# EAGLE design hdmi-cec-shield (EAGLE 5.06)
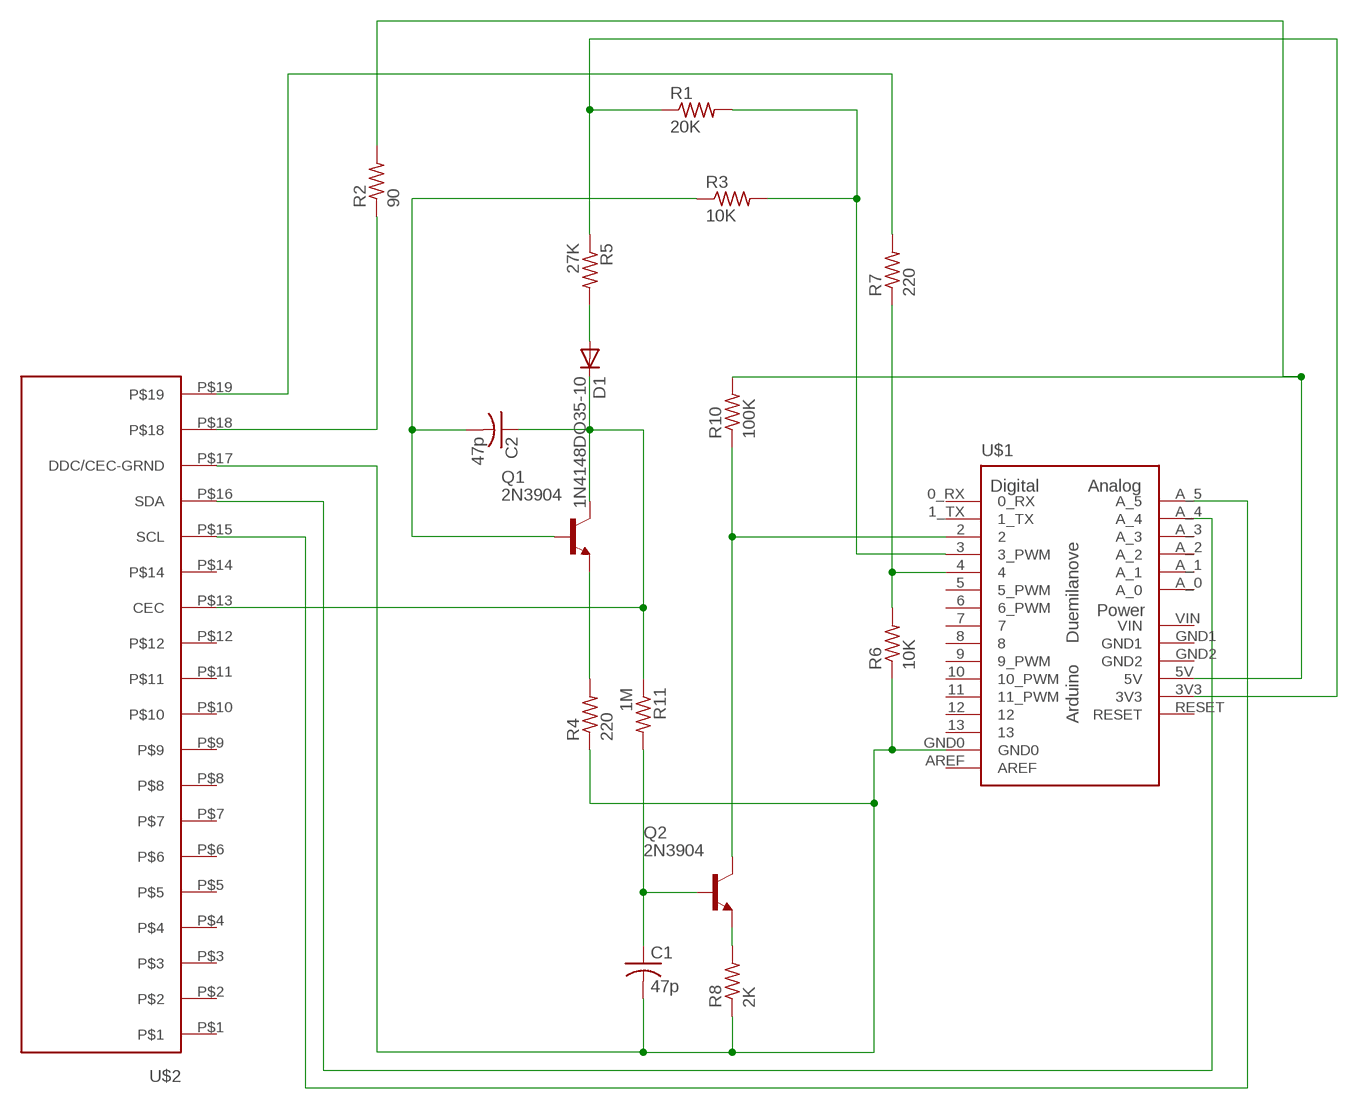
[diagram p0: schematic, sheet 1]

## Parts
C1  47p  C-US050-025X075  [C050-025X075]
C2  47p  C-US050-025X075  [C050-025X075]
D1  1N4148DO35-10  [DO35-10]
Q1  2N3904  [TO92]
Q2  2N3904  [TO92]
R1  20K  R-US_0207/10  [0207/10]
R2  90  R-US_0207/10  [0207/10]
R3  10K  R-US_0207/10  [0207/10]
R4  220  R-US_0207/10  [0207/10]
R5  27K  R-US_0207/10  [0207/10]
R6  10K  R-US_0207/10  [0207/10]
R7  220  R-US_0207/10  [0207/10]
R8  2K  R-US_0207/10  [0207/10]
R10  100K  R-US_0207/10  [0207/10]
R11  1M  R-US_0207/10  [0207/10]
U$1  ARDUINO-USBLONG_PADS_TEXT  [SHIELD]
U$2  HDMI-TYPE-A-RECEPTICALFCI10029449  [FCI-HDMI-TYPE-A-RECEPT]

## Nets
3.3V: R1.1 R5.1 U$1.3V3
5V: R2.2 R10.2 U$1.5V
GND0: C1.2 R4.1 R6.1 R8.1 U$1.GND0 U$2.P$17(DDC/CEC-GRND)
N$1: C2.2 Q1.2(B) R3.1
N$2: C1.1 Q2.2(B) R11.2
N$3: Q2.3(E) R8.2
N$4: Q2.1(C) R10.1 U$1.2
N$5: R2.1 U$2.P$18
N$6: C2.1 D1.C Q1.1(C) R11.1 U$2.P$13(CEC)
N$7: Q1.3(E) R4.2
N$8: R1.2 R3.2 U$1.3(3_PWM)
N$9: D1.A R5.2
N$10: R7.2 U$2.P$19
N$13: R6.2 R7.1 U$1.4
SCL: U$1.A_5 U$2.P$15(SCL)
SDA: U$1.A_4 U$2.P$16(SDA)
Unconnected: U$1.0_RX U$1.1_TX U$1.5(5_PWM) U$1.6(6_PWM) U$1.7 U$1.8 U$1.9(9_PWM) U$1.10(10_PWM) U$1.11(11_PWM) U$1.12 U$1.13 U$1.A_0 U$1.A_1 U$1.A_2 U$1.A_3 U$1.AREF U$1.GND1 U$1.GND2 U$1.RESET U$2.P$1 U$2.P$2 U$2.P$3 U$2.P$4 U$2.P$5 U$2.P$6 U$2.P$7 U$2.P$8 U$2.P$9 U$2.P$10 U$2.P$11 U$2.P$12 U$2.P$14

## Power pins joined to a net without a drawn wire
VIN: U$1.VIN

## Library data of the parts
C1 C2 = resistor:C-US: CAPACITOR, American symbol
D1 = diode:1N4148: DIODE
Q1 Q2 = transistor-neu-to92:2N3904: NPN TRANSISTOR
R1-R8 R10 R11 = resistor:R-US_: RESISTOR, American symbol
U$1 = Arduino-Various:ARDUINO-USB: The Ardiuno Duemilanove Pinouts layoutet as a Bare Shield. v0.5 Also for Arduino Diecimila. This is designed as a Part and has no Outline in the Dimension Layer. The Outline, when present, is drawed at the tPlace / bPlace Layer. Library by Stephanie Lange, http://www.k-ita.de/~sl/
U$2 = hdmi:HDMI-TYPE-A-RECEPTICAL

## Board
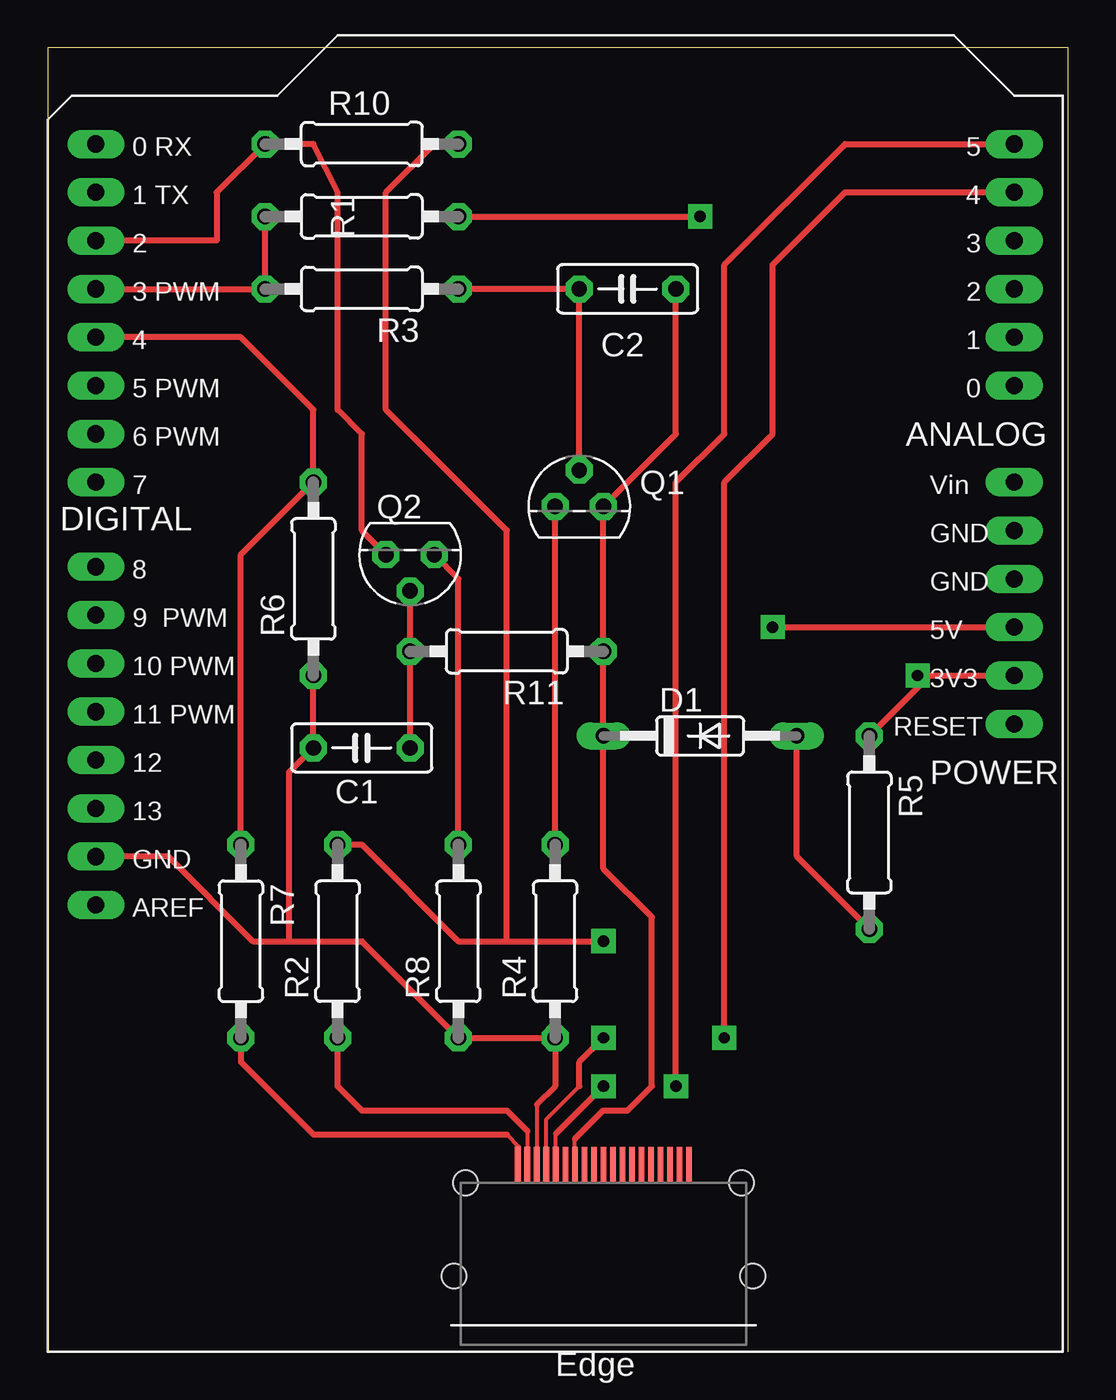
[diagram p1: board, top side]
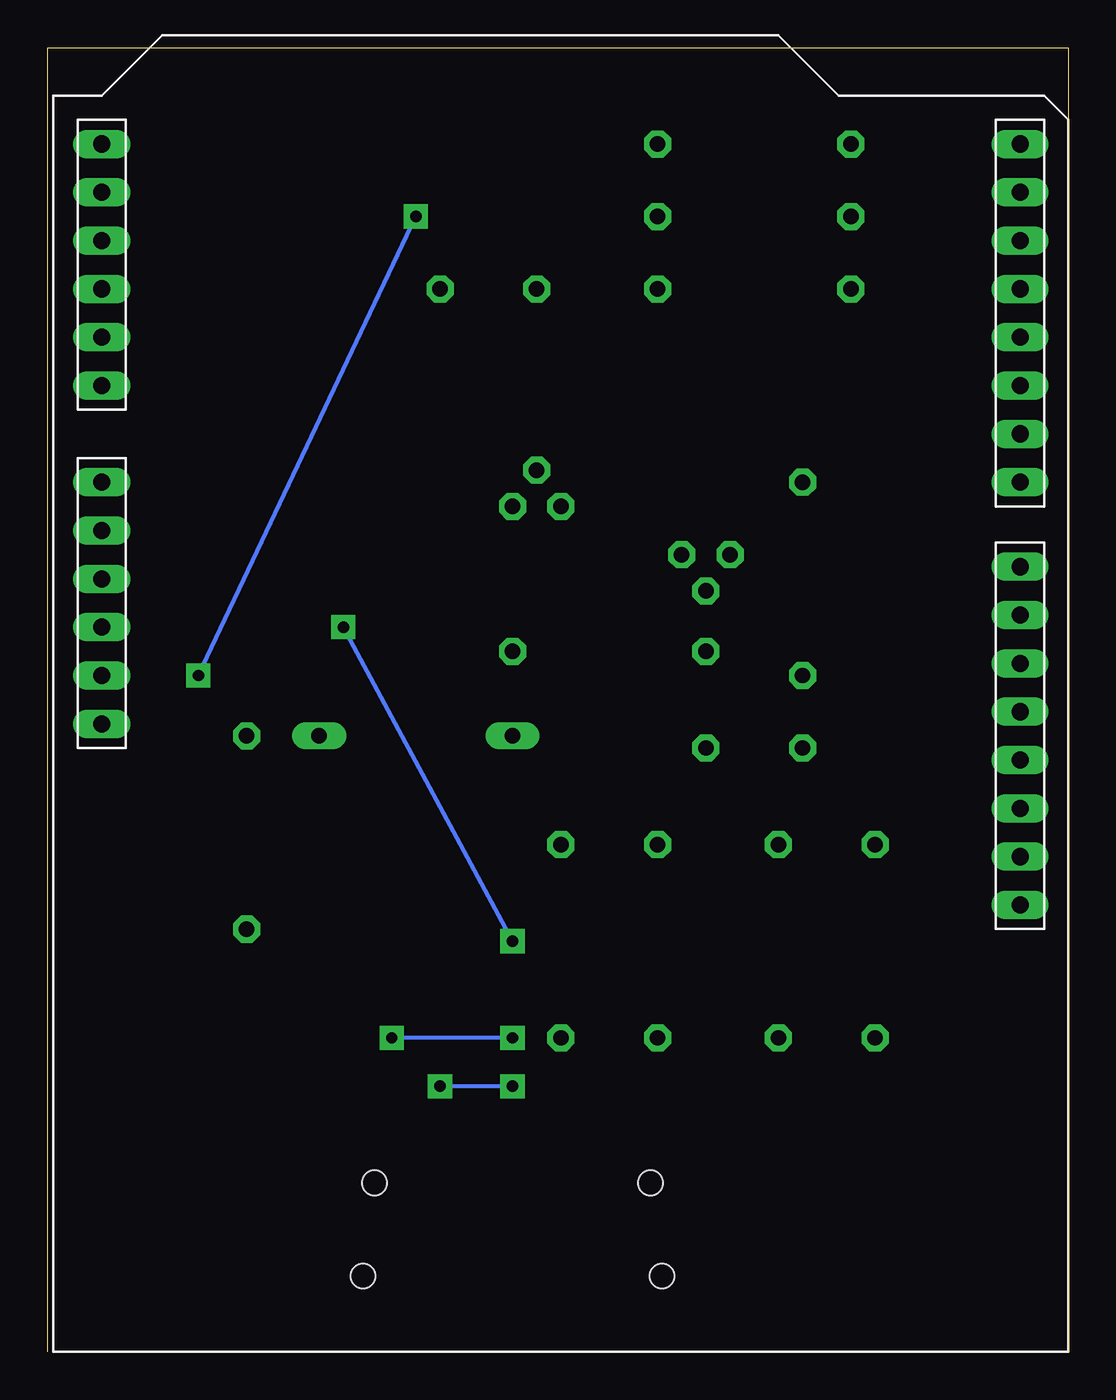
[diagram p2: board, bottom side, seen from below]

Size 53.65 x 68.57 mm. Coordinates in mm from the lower left corner, seen from the top.
Outline: 53.65,0 53.65,68.57 0,68.57 0,0
Copper layers (1*16): Top 0.035mm / dielectric 1.5mm / Bottom 0.035mm
Design rules "default *": minimum track width 10mil, minimum drill 24mil, track to track 8mil, track to pad 8mil, pad to pad 8mil, via to via 8mil, smd to smd 8mil, copper to edge 40mil, drill to drill 8mil, minimum pad ring 12mil, minimum via ring 8mil, stop-mask expansion 4mil, vias tented up to drill 0mil, thermal gap 10mil

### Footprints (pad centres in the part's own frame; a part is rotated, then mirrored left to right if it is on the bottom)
C050-025X075 = drill 0.813 octagon: 1 -2.54,0; 2 2.54,0
DO35-10 = drill 0.813 long: A 5.08,0; C -5.08,0
TO92 = drill 0.813 octagon: 1 1.27,0; 2 0,1.905; 3 -1.27,0
0207/10 = drill 0.813 octagon: 1 -5.08,0; 2 5.08,0
SHIELD = drill 0.9 pad 1.27 long: 0_RX -25.4,27.94; 1_TX -25.4,25.4; 2 -25.4,22.86; 3 -25.4,20.32; 3V3 22.86,0; 4 -25.4,17.78; 5 -25.4,15.24; 5V 22.86,2.54; 6 -25.4,12.7; 7 -25.4,10.16; 8 -25.4,5.715; 9 -25.4,3.175; 10 -25.4,0.635; 11 -25.4,-1.905; 12 -25.4,-4.445; 13 -25.4,-6.985; A_0 22.86,15.24; A_1 22.86,17.78; A_2 22.86,20.32; A_3 22.86,22.86; A_4 22.86,25.4; A_5 22.86,27.94; AREF -25.4,-12.065; GND0 -25.4,-9.525; GND1 22.86,7.62; GND2 22.86,5.08; RESET 22.86,-2.54; VIN 22.86,10.16
FCI-HDMI-TYPE-A-RECEPT = smd 1.9 x 0.3: P$1 -0.95,4.5; P$2 -0.95,4; P$3 -0.95,3.5; P$4 -0.95,3; P$5 -0.95,2.5; P$6 -0.95,2; P$7 -0.95,1.5; P$8 -0.95,1; P$9 -0.95,0.5; P$10 -0.95,0; P$11 -0.95,-0.5; P$12 -0.95,-1; P$13 -0.95,-1.5; P$14 -0.95,-2; P$15 -0.95,-2.5; P$16 -0.95,-3; P$17 -0.95,-3.5; P$18 -0.95,-4; P$19 -0.95,-4.5 | hole 1.3: 0,7.25; 0,-7.25; 4.9,7.85; 4.9,-7.85

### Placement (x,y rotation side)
C1  16.51,31.75 180 top
C2  30.48,55.88 180 top
D1  34.29,32.39 0 top
Q1  27.94,44.45 0 top
Q2  19.05,41.91 180 top
R1  16.51,59.69 180 top
R2  15.24,21.59 90 top
R3  16.51,55.88 180 top
R4  26.67,21.59 90 top
R5  43.18,27.3 270 top
R6  13.97,40.64 90 top
R7  10.16,21.59 270 top
R8  21.59,21.59 90 top
R10  16.51,63.5 0 top
R11  24.13,36.83 180 top
U$1  27.94,35.56 0 top
U$2  29.21,8.89 270 top

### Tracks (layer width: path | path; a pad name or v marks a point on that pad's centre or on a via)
3.3V  (via drill 0.6, 0.6 pad 1.27)
  Top 0.203: 46.35,35.56 v45.72,35.56
  Top 0.305: U$1.3V3 46.35,35.56 R5.1 | R1.1 v34.29,59.69
  Bottom 0.203: v45.72,35.56 v34.29,59.69
5V  (via drill 0.6, 0.6 pad 1.27)
  Top 0.305: R2.2 16.51,26.67 21.59,21.59 24.13,21.59 | 24.13,21.59 v29.21,21.59 | R10.2 20.32,63.5 17.78,60.96 17.78,49.53 24.13,43.18 24.13,21.59 | v38.1,38.1 U$1.5V
  Bottom 0.203: v29.21,21.59 v38.1,38.1
GND0
  Top 0.203: 25.71,13.01 U$2.P$17
  Top 0.305: 12.7,21.59 12.7,30.48 C1.2 R6.1 | 12.7,21.59 16.51,21.59 R8.1 R4.1 26.67,13.97 25.71,13.01 | 12.7,21.59 10.8,21.59 6.35,26.03 U$1.GND0
N$1
  Top 0.305: Q1.2 C2.2 R3.1
N$2
  Top 0.305: C1.1 R11.2 Q2.2
N$3
  Top 0.305: R8.2 21.59,40.64 Q2.3
N$4
  Top 0.305: U$1.2 8.89,58.42 8.89,60.96 R10.1 13.97,63.5 15.24,60.96 15.24,49.53 16.51,48.26 16.51,43.18 Q2.1
N$5
  Top 0.203: 25.21,11.62 U$2.P$18
  Top 0.305: 25.21,11.62 24.13,12.7 16.51,12.7 15.24,13.97 R2.1
N$6
  Top 0.203: U$2.P$13 27.71,11.2
  Top 0.305: C2.1 33.02,48.26 Q1.1 R11.1 D1.C 29.21,25.4 31.75,22.86 31.75,13.97 30.48,12.7 29.21,12.7 27.71,11.2
N$7
  Top 0.305: R4.2 Q1.3
N$8
  Top 0.305: R1.2 R3.2 U$1.3
N$9
  Top 0.305: R5.2 39.37,26.03 D1.A
N$10
  Top 0.203: 24.13,11.43 24.77,10.79 24.77,9.89 U$2.P$19
  Top 0.305: R7.2 10.16,15.24 13.97,11.43 24.13,11.43
N$12  (via drill 0.6 pad 1.27)
  other vias: 34.29,59.69
N$13
  Top 0.305: R7.1 10.16,41.91 R6.2 13.97,49.53 10.16,53.34 U$1.4
N$17  (via drill 0.6 pad 1.27)
  other vias: 29.21,21.59
SCL  (via drill 0.6 pad 1.27)
  Top 0.203: U$2.P$15 26.71,11.47
  Top 0.305: U$1.A_5 41.91,63.5 35.56,57.15 35.56,48.26 33.02,45.72 v33.02,13.97 | 26.71,11.47 v29.21,13.97
  Bottom 0.203: v29.21,13.97 v33.02,13.97
SDA  (via drill 0.6 pad 1.27)
  Top 0.203: U$2.P$16 26.21,12.24 27.94,13.97
  Top 0.305: U$1.A_4 41.91,60.96 38.1,57.15 38.1,48.26 35.56,45.72 v35.56,16.51 | 27.94,13.97 27.94,15.24 v29.21,16.51
  Bottom 0.203: v29.21,16.51 v35.56,16.51

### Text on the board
Document: SCL | JR1 | SDA | JR2 | JR1 | JR2 | SDA | 5V | SCL | HOTPLG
